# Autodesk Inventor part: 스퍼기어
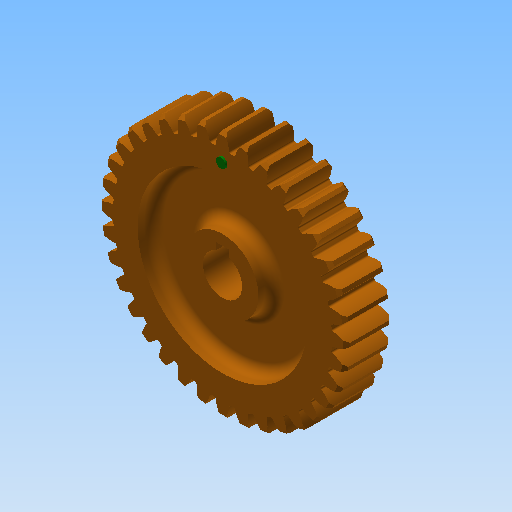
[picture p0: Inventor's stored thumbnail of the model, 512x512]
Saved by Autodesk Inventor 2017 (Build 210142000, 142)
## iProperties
Created: 2019-01
Part Number: 스퍼기어
Material: 알루미늄 6061
Document SubType Name: Modeling
Designer: mduedu
Density: 2.71 g/cm^3
Appearance: 주황색
Mass: 108.18 g
Surface Area: 169.519 cm^2
Volume: 39.919 cm^3
Author: mduedu
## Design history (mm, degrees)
sketch "스케치1"
  geometry: C1 r 33.5 at (0, 0); C2 r 36 at (0, 0); C3 r 38 at (0, 0); 1 further point
  constraints: 3 centre point, 3 coincident
  dimensions: "d0" = 67 diameter of C1; "d2" = 72 diameter of C2; "d3" = 76 diameter of C3
extrude "돌출1" new body sketch "스케치1" distance "d4" = 14; taper "d5" = 0 deg
sketch "스케치2"
  geometry: L1 (0, 0)-(-38, 0); L2 (0, 0)-(0, 38); L3 (-0.57, 0)-(-0.57, 37.996); L4 (-1.57, 0)-(-1.57, 35.966); L5 (-2.07, 0)-(-2.07, 33.436); A1 r 38 centre (0, 0) between (-38, 0) and (0, 38) reference; A2 r 9.246 centre (7.162, 32.926) between (-0.57, 37.996) and (-2.07, 33.436); A3 r 9.246 centre (-7.162, 32.926) between (2.07, 33.436) and (0.57, 37.996); A4 r 33.5 centre (0, 0) between (2.07, 33.436) and (-2.07, 33.436); A5 r 38 centre (0, 0) between (0.57, 37.996) and (-0.57, 37.996); 2 further points
  constraints: 12 point on circle, 10 end point, 4 centre point, 3 parallel, 3 symmetric about line, 2 coincident, 1 horizontal, 1 perpendicular, 5 other
  dimensions: "d6" = 0.5 distance between parallel lines of L4 L5; "d8" = 1 distance between parallel lines of L3 L4; "d9" = 1.57 distance between parallel lines of L2 L4
extrude "돌출2" join sketch "스케치2" stored distance "d10" = 14; taper "d11" = 0 deg
chamfer "모따기1" distance "d12" = 1; stored, may be unused: second distance "d13" = 2, angle "d14" = 45 deg
fillet "모깎기1" dims "d15" = 0.5
sketch "스케치3"
  geometry: C1 r 11 at (0, 0); 1 further point
  constraints: 1 centre point, 1 coincident
  dimensions: "d19" = 22 diameter of C1
extrude "돌출3" join sketch "스케치3" distance "d20" = 7; taper "d21" = 0 deg
sketch "스케치4"
  geometry: C1 r 11 at (0, 0); C2 r 26 at (0, 0); 1 further point
  constraints: 2 centre point, 2 coincident
  dimensions: "d23" = 22 diameter of C1; "d24" = 52 diameter of C2
extrude "돌출4" cut sketch "스케치4" distance "d25" = 5; taper "d26" = 0 deg
fillet "모깎기3" dims "d27" = 3
node "작업 평면1"
sketch "스케치5" dims "d28" = 60
  geometry: C1 r 1.5 at (0, 30); 2 further points
  constraints: 2 vertical alignment, 1 centre point, 1 coincident, 2 other
  dimensions: "d29" = 3 diameter of C1
extrude "돌출5" join sketch "스케치5" distance "d30" = 0.5; taper "d31" = 0 deg
sketch "스케치6"
  geometry: L1 (-2, 5.657)-(2, 5.657); L2 (2, 5.657)-(2, 7.8); L3 (2, 7.8)-(-2, 7.8); L4 (-2, 7.8)-(-2, 5.657); A1 r 6 centre (0, 0) between (-2, 5.657) and (2, 5.657); 1 further point
  constraints: 8 end point, 2 parallel, 2 point on circle, 1 centre point, 1 coincident, 1 horizontal, 1 perpendicular
  dimensions: "d32" = 13.8 dimension on A1 L3; "d34" = 4 distance of L2.end L3.end; "d35" = 12 diameter of A1
extrude "돌출6" cut sketch "스케치6" stored distance "d36" = 0.5; taper "d37" = 0 deg
chamfer "모따기2" distance "d38" = 1; stored, may be unused: second distance "d39" = 2, angle "d40" = 45 deg
node "솔리드1"
pattern_circular "원형 패턴1" dims angle "d17" = 360 deg
mirror "대칭1"
